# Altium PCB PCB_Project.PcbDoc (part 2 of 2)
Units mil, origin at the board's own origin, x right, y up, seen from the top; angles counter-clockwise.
Board outline 2079.64 x 1653.54 mil, 2 copper layers (Top Layer, Bottom Layer), stack 62 mil thick; 65 components, 34 nets, 154 pads, 107 vias.
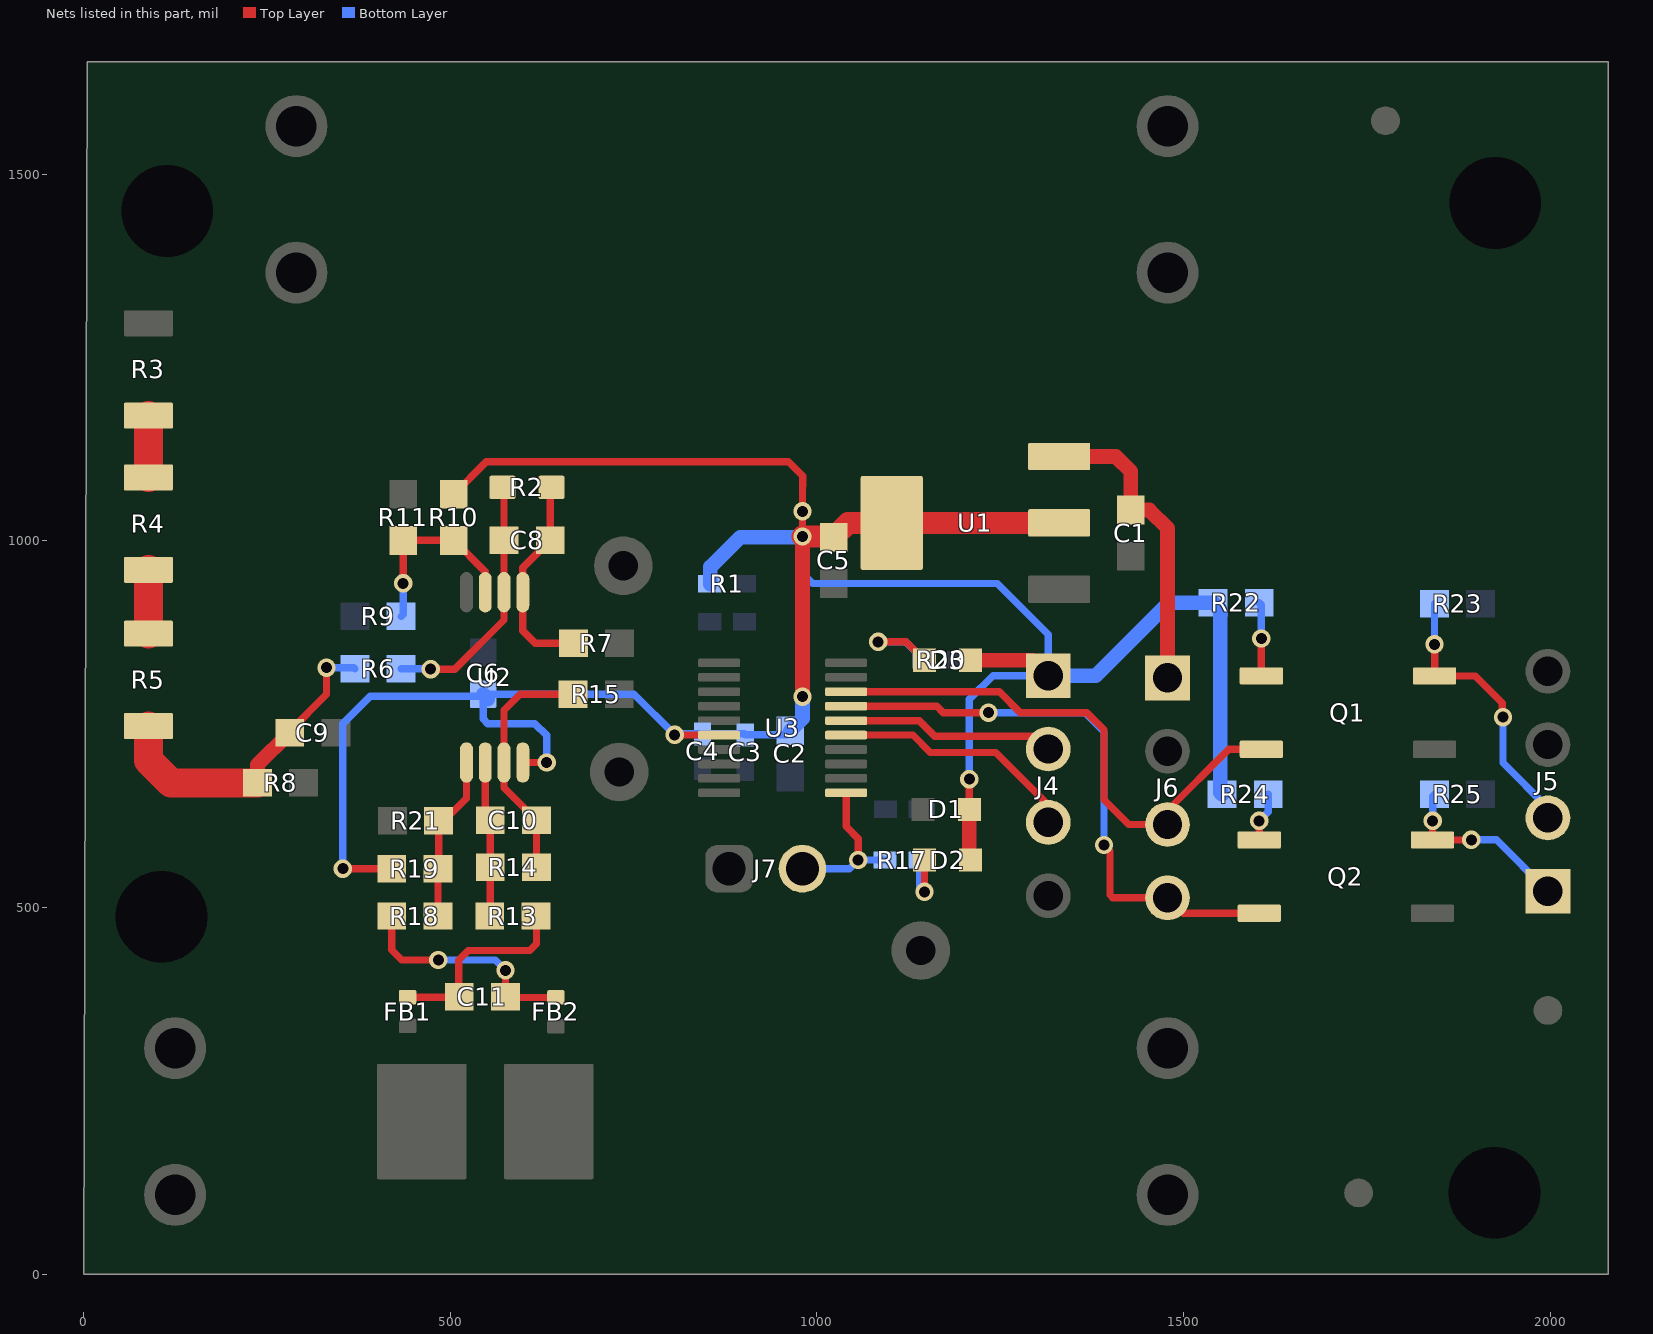
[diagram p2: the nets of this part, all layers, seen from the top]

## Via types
v1: diameter 25, hole 15, Top Layer to Bottom Layer, tented both sides, 107 vias

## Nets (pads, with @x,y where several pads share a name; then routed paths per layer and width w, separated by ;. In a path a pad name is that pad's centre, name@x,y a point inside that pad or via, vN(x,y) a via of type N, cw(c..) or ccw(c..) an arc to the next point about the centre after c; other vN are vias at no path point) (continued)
NetC8_1: C8.1 R2.2 R7.1 U2.1 | length 287.9
  Top Layer w10: R2.2@638.16,1072.92 636.43,1071.19 C8.1@636.43,1000.5 599.03,963.1 U2.1@599.03,929.88 599.03,877.36 616.14,860.25 R7.1@668.08,860.25
NetC8_2: C8.2 R2.1 R6.2 U2.2 | length 350.1
  Top Layer w10: v1(473.48,824.91) 506.4,824.91 573.44,891.95 U2.2@573.44,929.88 C8.2@573.44,1000.5 573.44,1070.71 R2.1@571.23,1072.92
  Bottom Layer w10: R6.2@433.13,825.31 473.08,825.31 v1(473.48,824.91)
NetC9_1: C9.1 R5.2 R6.1 R8.2 | length 433.3
  Top Layer w10: C9.1@281.17,738.28 281.17,740.3 331.36,790.49 v1(331.36,826.82)
  Top Layer w20: R8.2@237.21,669.75 237.21,694.32 C9.1@281.17,738.28
  Top Layer w40: R5.2@88.58,747.3 88.58,700.41 119.25,669.75 R8.2@237.21,669.75
  Bottom Layer w10: v1@341.8,826.82 368.63,826.82 R6.1@370.14,825.31
NetC10_1: C10.1 R14.2 R15.1 U2.7 | length 335.8
  Top Layer w10: R14.2@617.73,554.78 C10.1@617.73,618.76 573.44,663.05 U2.7@573.44,697.59 573.44,769.06 595.13,790.76 R15.1@667.63,790.76
NetC10_2: C10.2 R13.2 R14.1 U2.6 | length 212.5
  Top Layer w10: U2.6@547.85,697.59 547.85,625.65 C10.2@554.74,618.76 R14.1@554.74,554.78 554.74,489.06 R13.2@553.93,488.25
NetC11_1: C11.1 FB1.1 R13.1 | length 273.4
  Top Layer w10: FB1.1@441.99,377.66 511.9,377.66 C11.1@512.41,378.17 ; C11.1@511.83,378.76 511.83,428.3 524.82,441.29 608.61,441.29 617.73,450.41 617.73,487.45 R13.1@616.92,488.25
NetC11_2: C11.2 FB2.1 R18.1 | length 323.1
  Top Layer w10: R18.1@420.33,488.25 420.33,441.81 433.84,428.3 v1(483.93,428.3) v1@486.44,430.81 ; v1(575.41,414.23) 576.39,414.23 575.41,413.25 C11.2@575.41,378.17 576.39,377.19 FB2.1@644.14,377.19
  Bottom Layer w10: v1(483.93,428.3) 561.34,428.3 v1(575.41,414.23)
NetD3_1: D3.1 R20.2 | length 146.1
  Top Layer w10: v1(1083.66,862.2) 1121.61,862.2 D3.1@1146.8,837.02
  Bottom Layer w10: v1(1083.66,862.2) 1121.32,862.2 R20.2@1145.95,837.58
NetQ1_1: Q1.1 R22.2 | length 101.1
  Top Layer w10: Q1.1@1606.3,815.62 v1(1606.3,866.75)
  Bottom Layer w10: R22.2@1603.35,915.46 1606.3,912.5 v1(1606.3,866.75)
NetQ2_1: Q2.1 R24.2 | length 67.4
  Top Layer w10: Q2.1@1603.35,591.97 v1(1603.35,618.01)
  Bottom Layer w10: v1(1603.35,618.01) 1615.68,630.34 R24.2@1615.68,654.26
NetR3_1: R3.1 R4.2 | length 84.2
  Top Layer w40: R4.2@88.58,1086.33 R3.1@88.58,1170.57
NetR4_1: R4.1 R5.1 | length 87.1
  Top Layer w40: R5.1@88.58,873.29 R4.1@88.58,960.35
NetR9_2: R9.2 R10.1 R11.2 U2.3 | length 262.5
  Top Layer w10: v1(435.85,941.87) R11.2@435.85,1000.51 R10.1@505.14,1000.5 547.85,957.8 U2.3@547.85,929.88
  Bottom Layer w10: R9.2@433.13,896.79 435.85,899.51 v1(435.85,941.87)
NetR18_2: R18.2 R19.2 R21.2 U2.5 | length 229.6
  Top Layer w10: R18.2@483.32,488.25 R19.2@483.32,552.72 484.31,553.7 R21.2@484.31,618.08 491.29,618.08 522.26,649.04 U2.5@522.26,697.59
REACT: J7.2 R17.1 U3.11 | length 216.3
  Top Layer w10: U3.11@1040,656.25 1040,610.3 1056.52,593.78 v1(1056.52,564.54)
  Bottom Layer w10: J7.2@980.39,552.72 1044.7,552.72 v1(1056.52,564.54) R17.1@1093.23,564.54
SWCLK: J4.2 U3.16 | length 291.7
  Top Layer w10: U3.16@1040,754.68 1139.59,754.68 1161.03,733.24 1298.38,733.24 J4.2@1315.7,715.93
SWDIO: J4.3 U3.15 | length 338.9
  Top Layer w10: U3.15@1040,734.99 1131.16,734.99 1154.91,711.24 1244.18,711.24 1315.7,639.72 J4.3@1315.7,615.93
UART0_RX: J6.4 Q2.2 U3.17 | length 806.1
  Top Layer w10: U3.17@1040,774.36 1163.88,774.36 1172.62,765.62 v1(1234.25,765.62) ; v1(1391.73,585.04) 1399.8,576.97 1399.8,516.8 1403.61,512.99 J6.4@1478.35,512.99 1499.37,491.97 Q2.2@1603.35,491.97
  Bottom Layer w10: v1(1234.25,765.62) 1365.7,765.62 1391.73,739.58 v1(1391.73,585.04)
UART0_TX: J6.3 Q1.2 U3.18 | length 750.9
  Top Layer w10: U3.18@1040,794.05 1249.07,794.05 1277.5,765.62 1368.24,765.62 1391.73,742.13 1391.73,646.88 1425.61,612.99 J6.3@1478.35,612.99 1478.35,632.22 1561.75,715.62 Q1.2@1606.3,715.62
UART_ISO_RX: J5.2 Q1.4 R23.1 | length 389
  Top Layer w10: v1(1842.35,858.67) 1842.52,858.5 Q1.4@1842.52,815.62 1897.96,815.62 1934.87,778.71 1934.87,759.37 v1(1935.71,759.37)
  Bottom Layer w10: v1(1842.35,858.67) R23.1@1842.35,914 ; v1(1935.71,759.37) 1935.71,697.38 1997.05,636.05 J5.2@1997.05,622.05
UART_ISO_TX: J5.1 Q2.4 R25.1 | length 250.3
  Top Layer w10: v1(1839.84,618.01) 1839.57,617.73 Q2.4@1839.57,591.97 v1@1883.56,591.97 ; v1@1883.78,591.76 v1@1883.56,591.97 ; v1(1892.55,592.1) 1892.41,591.97 v1@1883.56,591.97
  Bottom Layer w10: v1(1839.84,618.01) 1839.84,651.75 R25.1@1842.35,654.26 ; v1(1892.55,592.1) 1926.99,592.1 J5.1@1997.05,522.05
VDD_3V3: C2.1 C3.1 C4.2 C5.1 C6.1 D1.2 D2.2 D3.2 J4.1 R1.2 R10.2 R19.1 R22.1 R24.1 U1.2 U1.4 U2.8 U3.6 | length 4021.6
  Top Layer w10: v1(353.58,552.72) R19.1@420.33,552.72 ; R10.2@505.14,1063.5 549.29,1107.64 961.49,1107.64 980.91,1088.22 980.91,1074.89 980.56,1074.53 v1(980.56,1040.2) v1(980.56,1005.86) ; U2.8@599.03,697.59 v1(631.51,697.59) ; v1@816.97,734.65 817.32,734.99 U3.6@866.77,734.99 ; D1.2@1207.97,633.76 v1(1207.97,674.95)
  Top Layer w20: v1(980.39,787.37) 980.39,1005.69 v1(980.56,1005.86) ; D1.2@1207.97,633.76 1207.97,566.36 D2.2@1209.79,564.54 ; D3.2@1209.79,837.02 1294.61,837.02 J4.1@1315.7,815.93
  Top Layer w30: v1(980.56,1005.86) 1021.95,1005.86 C5.1@1023.08,1004.74 1042.69,1024.35 U1.4@1102.23,1024.35 U1.2@1330.58,1024.35
  Bottom Layer w10: v1(353.58,552.72) 353.58,750.66 390.81,787.88 542.08,787.88 C6.1@544.95,790.76 ; v1(631.51,697.59) 631.51,734.65 615.5,750.66 551.43,750.66 544.95,757.13 C6.1@544.95,790.76 ; C2.1@963.83,740.9 958.18,735.25 C3.1@902.4,735.25 901.03,736.62 C4.2@844.24,736.62 807.59,736.62 v1(806.22,735.25) 750.72,790.76 C6.1@544.95,790.76 ; v1(980.56,1005.86) 980.56,955.56 994.38,941.74 1246.07,941.74 1315.7,872.12 J4.1@1315.7,815.93 1240.25,815.93 1207.97,783.65 v1(1207.97,674.95)
  Bottom Layer w20: C6.1@544.95,790.76 C6.1@551.44,784.27 ; R1.2@854.91,940.81 854.91,964.13 895.52,1004.74 979.44,1004.74 v1(980.56,1005.86) ; C2.1@963.83,740.9 980.56,757.63 980.56,787.2 v1(980.39,787.37) ; J4.1@1315.7,815.93 1380.51,815.93 1480.04,915.46 R22.1@1540.35,915.46 1550.18,905.63 1550.18,656.76 R24.1@1552.69,654.26
VIN: C1.1 J6.1 U1.3 | length 423.3
  Top Layer w20: U1.3@1330.58,1114.9 1408.01,1114.9 1428.35,1094.56 C1.1@1428.35,1041.84 1453.7,1041.84 1478.35,1017.2 J6.1@1478.35,812.99
YLED: D2.1 R17.2 | length 89.2
  Top Layer w10: v1(1146.8,521.26) D2.1@1146.8,564.54
  Bottom Layer w10: R17.2@1140.48,564.54 1140.48,527.58 v1(1146.8,521.26)
pads on no net: FID1.1 FID2.1 FID3.1 MH1.1 MH2.1 MH3.1 MH4.1 U3.3 U3.4 U3.8 U3.9 U3.10 U3.13 U3.14 U3.19 U3.20

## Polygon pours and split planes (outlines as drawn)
A_Netural_OUT on Top Layer "TOP_LAYER_A_NETURAL_OUT_P006" (solid, remove dead copper, pour order 6): 578.36,359.47 1528.35,359.47 1528.35,27.36 1526.08,25.1 577.91,25.1 578.36,25.55
A_Netural_IN on Top Layer "TOP_LAYER_A_NETURAL_IN_P004" (solid, remove dead copper, pour order 4): 52.17,394.91 276.69,394.91 278.66,396.87 278.66,1156.24 1528.35,1156.24 1528.35,388.12 525.21,388.12 525.21,28.06 522.64,25.49 522.54,25.59 50.2,25.59 50.2,392.94
A_LIN_IN on Top Layer "TOP_LAYER_A_LIN_IN_P001" (solid, remove dead copper, pour order 1): 219.49,1637.8 1535.83,1637.8 1535.83,1317.91 219.49,1317.91
VDD_3V3 on Top Layer "TOP_LAYER_VDD_3V3_P000" (solid, remove dead copper, pour order 0): 845.67,1016.84 915.81,1086.98 1143.57,1086.98 1143.57,941.74 845.67,941.74
A_Netural_OUT on Bottom Layer "BOTTOM_LAYER_A_NETURAL_OUT_P007" (solid, remove dead copper, pour order 7): 578.36,359.47 1528.35,359.47 1528.35,27.36 580.81,27.36 578.54,25.1 578.36,25.28
A_LIN_IN on Bottom Layer "BOTTOM_LAYER_A_LIN_IN_P005" (solid, remove dead copper, pour order 5): 219.49,1628.05 1535.83,1628.05 1535.83,1317.91 219.49,1317.91 219.49,1628.05
A_Netural_IN on Bottom Layer "BOTTOM_LAYER_A_NETURAL_IN_P003" (solid, remove dead copper, pour order 3): 51.18,25.59 52.17,24.61 522.64,24.61 522.64,377.79 512.31,388.12 1528.35,388.12 1528.35,1156.24 278.66,1156.24 278.66,396.87 54.13,396.87 50.2,392.94 50.2,25.59

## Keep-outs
Keep-Out Layer:
  text ".Layer_Name" at 577,-858.49 h60

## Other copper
Top Layer:
  text ".Layer_Name" at 577,-858.49 h60
Bottom Layer:
  text ".Layer_Name" at 577,-858.49 h60

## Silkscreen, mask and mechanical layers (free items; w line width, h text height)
Top Overlay:
  text "Live_IN" at 383.58,1449.8 h60
  text "Live_OUT" at 1170,1437.99 h60
  text "3V3" at 1253.55,797.22 h30 r90
  text "VIN" at 1417.9,792.83 h30 r90
  text "ISO_VDD" at 1932.35,761.84 h30 r90
  text "CLK" at 1253.68,688.34 h30 r90
  text "GND" at 1419.87,683.29 h30 r90
  text "GND" at 1937.86,681.98 h30 r90
  text "RX" at 1933.34,598 h30 r90
  text "TX" at 1419.23,595.4 h30 r90
  text "DIO" at 1253.68,592.94 h30 r90
  text "TX" at 1929.07,498.39 h30 r90
  text "GND" at 1253.68,494.07 h30 r90
  text "RX" at 1417.59,491.7 h30 r90
  text "Neutral_OUT" at 1092.42,192.38 h60
  text "Neutral_IN" at 194.88,54.13 h60
  text "E-metering with M0C" at 777.95,47.15 h70
  text ".Layer_Name" at 577,-858.49 h60
Bottom Overlay:
  text ".Layer_Name" at 577,-858.49 h60
Top Paste:
  text ".Layer_Name" at 577,-858.49 h60
Bottom Paste:
  text ".Layer_Name" at 577,-858.49 h60
Top Solder:
  text ".Layer_Name" at 577,-858.49 h60
  text ".Layer_Name" at 577,-858.49 h60
Bottom Solder:
  text ".Layer_Name" at 577,-858.49 h60
Drill Guide:
  text ".Layer_Name" at 577,-858.49 h60
M1 Board Outline:
  the board outline again, w10
  text ".Layer_Name" at 577,-858.49 h60
M2 Board Dimensions:
  rectangle: 125,-400 500,-275
  rectangle: 0,-275 125,-150
  lines w7: 0,-275 1000,-275 ; 125,-400 125,-150 ; 250,-400 250,-150 ; 500,-400 500,-150 ; 750,-400 750,-150 ; 0,-400 0,-150 1000,-150 1000,-400 0,-400
  text ".Layer_Name" at 577,-858.49 h60
M3 3D STEP Top:
  text ".Layer_Name" at 577,-858.49 h60
M4 3D STEP Bottom:
  text ".Layer_Name" at 577,-858.49 h60
M5 Assembly Top:
  lines w10: -292,-930.17 6308,-930.17 ; -292,-726.83 6310,-726.83 ; -292,-523.5 -292,-1133.5 3713,-1133.5 6310,-1133.5 6310,-523.5 -291.5,-523.5 -291.5,-1133.5 1284,-1133.5 ; 2173,-1133.5 2173,-523.5 ; 3440,-726.83 3440,-523.5 ; 4280,-726.83 4280,-523.5 ; 4902,-1140 4902,-937.17
  text "COMPONENTS MARKED 'DNP' SHOULD NOT BE POPULATED." at 1153.5,-318.5 h60
  text "ASSEMBLY VARIANT:" at 1153,-434 h60
  text ".VariantName" at 2189,-434 h60
  text "PCB VIEWED FROM TOP SIDE" at -228.5,-655.67 h60
  text "BOARD #:" at 2248,-655.67 h60
  text ".PRJ_Number" at 2793.5,-655.67 h60
  text "REV:" at 3638,-655.67 h60
  text ".PCB_Rev" at 3929.5,-655.67 h60
  text "SVN REV:" at 4476,-655.67 h60
  text ".VersionControl_RevNumber" at 4982,-655.67 h60
  text "PLOT NAME =" at -228.5,-1064.34 h60
  text ".plot_File_Name" at 577,-1064.34 h60
  text "GENERATED    :" at 2250,-1064.34 h60
  text ".Print_Date" at 3119.5,-1064.34 h60
  text ".Print_Time" at 3848.5,-1064.34 h60
  text "TEXAS INSTRUMENTS" at 5113,-1064.34 h60
M6 Assembly Bottom:
  lines w10: -292.5,-727.33 6309.5,-727.33 ; -290.5,-930.67 6309.5,-930.67 ; 1115.5,-1140.5 1115.5,-937.67 ; 1737.5,-727.33 1737.5,-524 ; 2577.5,-727.33 2577.5,-524 ; 3844.5,-1134 3844.5,-524 ; 4733.5,-1134 6309,-1134 6309,-524 -292.5,-524 -292.5,-1134 2304.5,-1134 6309.5,-1134 6309.5,-524
  text "COMPONENTS MARKED 'DNP' SHOULD NOT BE POPULATED." at 6102,-318 h60
  text ".VariantName" at 5058,-434 h60
  text "ASSEMBLY VARIANT:" at 6097,-434 h60
  text ".VersionControl_RevNumber" at 1035.5,-656.17 h60
  text "SVN REV:" at 1541.5,-656.17 h60
  text ".PCB_Rev" at 2088,-656.17 h60
  text "REV:" at 2379.5,-656.17 h60
  text ".PRJ_Number" at 3224,-656.17 h60
  text "BOARD #:" at 3769.5,-656.17 h60
  text "PCB VIEWED FROM BOTTOM SIDE" at 6246,-656.17 h60
  text "TEXAS INSTRUMENTS" at 904.5,-1064.84 h60
  text ".Print_Time" at 2169,-1064.84 h60
  text ".Print_Date" at 2898,-1064.84 h60
  text "GENERATED    :" at 3767.5,-1064.84 h60
  text ".plot_File_Name" at 5440.5,-1064.84 h60
  text "PLOT NAME =" at 6246,-1064.84 h60
M9 Title Sheet:
  drawing of 56 lines, arcs and shapes, not listed
  text "1" at 1058.34,13381.39 h70
  text "2" at 4384,13381.39 h70
  text "3" at 7714,13381.39 h70
  text "4" at 11049,13381.39 h70
  text "5" at 14374,13381.39 h70
  text "6" at 17709,13381.39 h70
  text "A" at -463,11603.39 h70
  text "A" at 19237,11603.39 h70
  text "B" at -463,7853.39 h70
  text "B" at 19237,7853.39 h70
  text "C" at -463,4103.39 h70
  text "C" at 19237,4103.39 h70
  text "D" at -463,353.39 h70
  text "D" at 19237,353.39 h70
  text "PROJECT TITLE:" at 16143,268.39 h45
  text ".PRJ_Title" at 16193,135.06 h70
  text "DESIGNED FOR:" at 16143,-32.61 h45
  text ".PRJ_Customer" at 16193,-172.61 h70
  text "FILE NAME:" at 16143,-332.61 h45
  text ".PCB_File_Name_No_Path" at 16193,-452.61 h70
  text "Texas Instruments (TI) and/or its licensors do not warrant the accuracy or completeness of this specification" at 11173.5,-614.45 h45
  text "ENGINEER:" at 16143,-622.61 h45
  text "LAYOUT BY:" at 17648,-622.61 h45
  text "or any information contained therein. TI and/or its licensors do not warrant that this design will meet" at 11128.51,-727.11 h45
  text ".PRJ_Engineer" at 16193,-777.6 h70
  text ".PCB_Layout" at 17698.5,-777.6 h70
  text "the specifications, will be suitable for your application or fit for any particular purpose, or will operate in" at 11128.51,-839.78 h45
  text ".Layer_Name" at 577,-858.49 h60
  text "ALTIUM DESIGNER VERSION:" at 17648,-932.61 h45
  text "an implementation. TI and/or its licensors do not warrant that the design is production worthy. You should" at 11128.51,-952.44 h45
  text "completely validate and test your design implementation to confirm the system functionality for your application." at 11173.5,-1065.11 h45
  text ".print_Scale" at 16193,-1065.94 h70
  text ".Application_BuildNumber" at 17698.5,-1065.94 h70
  text "1" at 1058.34,-1318.61 h70
  text "2" at 4384,-1318.61 h70
  text "3" at 7714,-1318.61 h70
  text "4" at 11049,-1318.61 h70
  text "5" at 14374,-1318.61 h70
  text "6" at 17709,-1318.61 h70
M10 Fab Notes:
  drawing of 189 lines, arcs and shapes, not listed
  text "DESIGN INFORMATION" at 17178.02,6365.17 h60
  text "MIN. TRACK WIDTH:" at 16533.46,6233.05 h60
  text "8" at 17629.7,6233.05 h60
  text "MIL" at 17784.46,6233.05 h60
  text "MIN. CLEARANCE:" at 16533.46,6108.92 h60
  text "MIL" at 17784.46,6108.92 h60
  text "7.874" at 17459.65,6104.33 h60
  text "MIN. VIA PAD SIZE:" at 16533.46,5984.8 h60
  text "24" at 17599.71,5984.8 h60
  text "MIL" at 17784.46,5984.8 h60
  text "0.05mm (2MIL)" at 17228.46,5854.9 h60
  text "MINIMUM ANNULAR RING" at 16204.23,5846.67 h60
  text "EXTERNAL" at 17936.46,5846.67 h60
  text "PER" at 16404.23,5736.55 h60
  text "IPC-D-275 CLASS 2 LEVEL C" at 16624.23,5736.54 h60
  text "MIL, HOLES" at 18112.46,5636.07 h60
  text "+/-" at 17720,5627.48 h60
  text "+/-" at 18574,5627.48 h60
  text "REGISTRATION TOLERANCES:" at 16204.23,5626.42 h60
  text "METAL" at 17404,5626.42 h60
  text "5" at 17980.2,5626.42 h60
  text "3" at 18813.2,5626.42 h60
  text "MIL" at 18929.46,5626.42 h60
  text "HOLE SIZE TOLERANCE (UNLESS OTHERWISE SPECIFIED):" at 16204.23,5528.1 h60
  text "+/-" at 18574,5525.23 h60
  text "3" at 18813.2,5524.17 h60
  text "MIL" at 18929.46,5524.17 h60
  text "MATERIAL:" at 16129.46,5386.52 h60
  text "FR-4 High Tg" at 17115.9,5258 h60
  text "X" at 16971.46,5250.01 h60
  text "FR-4" at 16550.46,5245.49 h60
  text "OTHER" at 18038.46,5245.49 h60
  text "62 MIL (1.6mm) +/-10%" at 16870.56,5102.46 h60
  text "X" at 16750.46,5100.01 h60
  text "THICKNESS:" at 16204.23,5094.24 h60
  text "OTHER" at 18155.46,5094.24 h60
  text "TOLERANCE:" at 16204.23,4955.92 h60
  text "X" at 17052.46,4955.92 h60
  text "ANSI IPC-6012 TYPE 3 CLASS 2" at 17230.48,4955.92 h60
  text "OTHER +/-" at 17230.46,4811.73 h60
  text "BOW & TWIST:" at 16204.23,4666.54 h60
  text "X" at 17052.46,4666.54 h60
  text "ANSI IPC-6012 TYPE 3 CLASS 2" at 17230.48,4666.54 h60
  text "OTHER +/-" at 17230.46,4519.85 h60
  text "DRILLING:" at 16129.46,4389.23 h60
  text "NC_DRILL FILES" at 17890.46,4284.04 h60
  text "REFERENCE:" at 16204.23,4280.1 h60
  text "X" at 16861.46,4280.01 h60
  text "AS SHOWN" at 17039.46,4280.1 h60
  text "X" at 17762.46,4280.1 h60
  text "OTHER" at 18188.46,4137.85 h60
  text "PTH COPPER THICKNESS:" at 16203.91,4134.32 h60
  text "X" at 17343.14,4134.32 h60
  text "20-30 um" at 17471.14,4134.32 h60
  text "BOARD FINISH:" at 16129.46,3986.73 h60
  text "SILKSCREEN:" at 16284.68,3876.6 h60
  text "X" at 17242.46,3876.6 h60
  text "TOP" at 17359.46,3876.6 h60
  text "X" at 17752.46,3876.6 h60
  text "BOTTOM" at 17870.46,3876.6 h60
  text "SILKSCREEN COLOR:" at 16284.68,3721.41 h60
  text "X" at 17241.46,3721.41 h60
  text "WHITE" at 17359.46,3721.41 h60
  text "OTHER" at 17870.46,3721.41 h60
  text "X" at 17372.46,3577.96 h60
  text "GREEN" at 17490.46,3577.96 h60
  text "OTHER" at 18108.46,3577.96 h60
  text "SOLDER RESIST COLOR:" at 16284.68,3571.1 h60
  text "X" at 17372.46,3423.71 h60
  text "MATTE" at 17490.46,3423.71 h60
  text "SEMI-GLOSS" at 18108,3423.07 h60
  text "IMMERSION GOLD (ENIG)" at 17190.46,3250.94 h60
  text "ENEPIG" at 18528,3243.72 h60
  text "SURFACE FINISH:" at 16129.46,3242.72 h60
  text "X" at 17012.46,3242.72 h60
  text "IMM. TIN/SILVER OR EQUIV" at 16459,3105.4 h60
  text "OTHER" at 17890.46,3101.47 h60
  text "ARRAY/PANEL:" at 16129.46,2946.09 h60
  text "CUT AND TRIM PER M1 BOARD OUTLINE" at 17190.46,2937.87 h60
  text "N.C. ROUTE" at 17190.46,2801.9 h60
  text "X" at 17878.46,2801.9 h60
  text "V. SCORE" at 18056.46,2801.9 h60
  text "CERTIFICATION:" at 16129.46,2672.77 h60
  text "MATERIALS AND WORKMANSHIP FOR ALL PCBS" at 16854.46,2672.77 h60
  text "TO MEET OR EXCEED THE REQUIREMENTS OF:" at 16854.46,2578.71 h60
  text "X" at 16491.97,2450.08 h60
  text "ANSI IPC-A-600F CLASS ->" at 16619.96,2450.08 h60
  text "X" at 18267.97,2450.08 h60
  text "2" at 18377.96,2450.08 h60
  text "1" at 18062.96,2448.58 h60
  text "3" at 18731.96,2448.58 h60
  text "X" at 17303.97,2302.39 h60
  text "RoHS" at 17431.96,2302.39 h60
  text "OTHER" at 18076.36,2302.39 h60
  text "PER ORDER" at 18473.42,2302.39 h60
  text "ALL BOARDS MUST MEET OR EXCEED UL94-V0 REQUIREMENTS." at 16157,2148.57 h60
  text "PCB MUST BEAR THE UL94V-0 UL REGISTERED MATERIAL ID NUMBER" at 16157,2032.5 h60
  text "ADDITIONAL REQUIREMENTS:" at 16129.46,1863.08 h60
  text "MICROSECTION:" at 16204.23,1755.95 h60
  text "YES" at 17109.96,1755.95 h60
  text "REQUIRED" at 17971.46,1611.62 h60
  text "BARE BOARD ELEC. TEST:" at 16204.23,1608.76 h60
  text "NONE" at 17509.96,1608.76 h60
  text "X" at 17853.46,1608.76 h60
  text "PER ORDER" at 18563.46,1608.76 h60
  text "XX MIL VIAS REQUIRE NON-CONDUCTIVE FILL AND PLANARIZE" at 16372.38,1403.82 h59
  text "XX MIL VIAS REQUIRE CONDUCTIVE FILL AND PLANARIZE" at 16380.38,1299.84 h60
  text "OUTER XX MIL TRACES REQUIRE 50 OHM SINGLE-ENDED IMPEDANCE" at 16379.39,1136.46 h58
  text "LAYER 2 & 3 (INNER LAYERS) XX MIL WIDE, XX MIL SPACE / TRACES REQUIRE 100 OHM DIFFERENTIAL IMPEDANCE" at 16371.39,900.74 h60
  text ".Layer_Name" at 577,-858.49 h60
M11 Gerber Information:
  lines w10: -292,-930.17 6308,-930.17 ; -292,-726.83 6310,-726.83 ; -292,-523.5 -292,-1133.5 3713,-1133.5 6310,-1133.5 6310,-523.5 -291.5,-523.5 -291.5,-1133.5 1284,-1133.5 ; 2173,-1133.5 2173,-523.5 ; 3440,-726.83 3440,-523.5 ; 4280,-726.83 4280,-523.5 ; 4902,-1140 4902,-937.17
  text "ALL ARTWORK VIEWED FROM TOP SIDE" at -228.5,-655.67 h60
  text "BOARD #:" at 2248,-655.67 h60
  text ".PRJ_Number" at 2793.5,-655.67 h60
  text "REV:" at 3638,-655.67 h60
  text ".PCB_Rev" at 3929.5,-655.67 h60
  text "SVN REV:" at 4476,-655.67 h60
  text ".VersionControl_RevNumber" at 4982,-655.67 h60
  text "LAYER NAME =" at -228.5,-858.49 h60
  text "PLOT NAME =" at -228.5,-1064.34 h60
  text ".plot_File_Name" at 577,-1064.34 h60
  text "GENERATED    :" at 2250,-1064.34 h60
  text ".Print_Date" at 3119.5,-1064.34 h60
  text ".Print_Time" at 3848.5,-1064.34 h60
  text "TEXAS INSTRUMENTS" at 5113,-1064.34 h60
M12 Stackup:
  drawing of 191 lines, arcs and shapes, not listed
  text "Layer" at 14605.06,13091.48 h60
  text "Name" at 15014.97,13091.48 h60
  text "Material" at 15944.72,13091.48 h60
  text "Thickness" at 16804.48,13091.48 h60
  text "Constant" at 17454.32,13091.48 h60
  text "Board Layer Stack" at 18024.18,13091.48 h60
  text "Top Overlay" at 15014.97,12971.48 h60
  text "Top Solder" at 15014.97,12851.48 h60
  text "Solder Resist" at 15944.72,12851.48 h60
  text "0.40mil" at 16804.48,12851.48 h60
  text "3.5" at 17454.32,12851.48 h60
  text "1" at 14605.06,12731.48 h60
  text "Top Layer" at 15014.97,12731.48 h60
  text "1.40mil" at 16804.48,12731.48 h60
  text "Dielectric1" at 15014.97,12611.48 h60
  text "FR-4 High Tg" at 15944.72,12611.48 h60
  text "59.20mil" at 16804.48,12611.48 h60
  text "4.8" at 17454.32,12611.48 h60
  text "2" at 14605.06,12491.48 h60
  text "Bottom Layer" at 15014.97,12491.48 h60
  text "1.40mil" at 16804.48,12491.48 h60
  text "Bottom Solder" at 15014.97,12371.48 h60
  text "Solder Resist" at 15944.72,12371.48 h60
  text "0.40mil" at 16804.48,12371.48 h60
  text "3.5" at 17454.32,12371.48 h60
  text "Bottom Overlay" at 15014.97,12251.48 h60
  text ".Layer_Name" at 577,-858.49 h60
M13 Component Bodies Top:
  text ".Layer_Name" at 577,-858.49 h60
M14 Component Bodies Bottom:
  text ".Layer_Name" at 577,-858.49 h60
M15 Courtyards Top:
  text ".Layer_Name" at 577,-858.49 h60
M16 Courtyards Bottom:
  text ".Layer_Name" at 577,-858.49 h60
Drill Drawing:
  circle w10: c5443.72,3159.96 r27.63
  lines w10: 5416.09,2814.63 5471.34,2814.63 5443.72,2759.38 5416.09,2814.63 ; 5416.09,2883.7 5471.34,2883.7 5471.34,2938.95 5416.09,2938.95 5416.09,2883.7 ; 5416.09,3021.83 5429.9,3021.83 5443.72,3008.02 5457.53,3021.83 5471.34,3021.83 5457.53,3035.64 5471.34,3049.46 5457.53,3049.46 5443.72,3063.27 5429.9,3049.46 5416.09,3049.46 5429.9,3035.64 5416.09,3021.83 ; 5416.09,3256.66 5443.72,3270.47 5471.34,3256.66 5457.53,3284.28 5471.34,3311.91 5443.72,3298.1 5416.09,3311.91 5429.9,3284.28 5416.09,3256.66
  lines w12: 5366,2722.08 8597.49,2722.08 ; 5366,3343.68 8597.49,3343.68 ; 5703.86,2597.76 5703.86,3468 ; 6035.86,2597.76 6035.86,3468 ; 6672.43,2597.76 6672.43,3468 ; 6931.57,2597.76 6931.57,3468 ; 7306.72,2597.76 7306.72,3468 ; 8031.05,2597.76 8031.05,3468 ; 5366,2597.76 8597.49,2597.76 8597.49,3468 5366,3468 5366,2597.76
  text "Symbol" at 5440.59,3380.98 h72
  text "Quantity" at 5741.16,3380.98 h72
  text "Finished Hole Size" at 6073.16,3380.98 h72
  text "Plated" at 6709.72,3380.98 h72
  text "Hole Type" at 6968.86,3380.98 h72
  text "Drill Layer Pair" at 7344.02,3380.98 h72
  text "Hole Tolerance" at 8068.35,3380.98 h72
  text "4" at 5741.16,3256.66 h60
  text "125.00mil (3.175mm)" at 6073.16,3256.66 h60
  text "NPTH" at 6709.72,3256.66 h60
  text "Round" at 6968.86,3256.66 h60
  text "Top Layer - Bottom Layer" at 7344.02,3256.66 h60
  text "107" at 5741.16,3132.34 h60
  text "15.00mil (0.381mm)" at 6073.16,3132.34 h60
  text "PTH" at 6709.72,3132.34 h60
  text "Round" at 6968.86,3132.34 h60
  text "Top Layer - Bottom Layer" at 7344.02,3132.34 h60
  text "15" at 5741.16,3008.02 h60
  text "40.00mil (1.016mm)" at 6073.16,3008.02 h60
  text "PTH" at 6709.72,3008.02 h60
  text "Round" at 6968.86,3008.02 h60
  text "Top Layer - Bottom Layer" at 7344.02,3008.02 h60
  text "2" at 5741.16,2883.7 h60
  text "45.28mil (1.150mm)" at 6073.16,2883.7 h60
  text "PTH" at 6709.72,2883.7 h60
  text "Round" at 6968.86,2883.7 h60
  text "Top Layer - Bottom Layer" at 7344.02,2883.7 h60
  text "8" at 5741.16,2759.38 h60
  text "55.12mil (1.400mm)" at 6073.16,2759.38 h60
  text "PTH" at 6709.72,2759.38 h60
  text "Round" at 6968.86,2759.38 h60
  text "Top Layer - Bottom Layer" at 7344.02,2759.38 h60
  text "136 Total" at 5741.16,2635.06 h60
  text ".Layer_Name" at 577,-858.49 h60
M17 Embedded Cavity:
  text ".Layer_Name" at 577,-858.49 h60
M18 Embedded Assembly:
  text ".Layer_Name" at 577,-858.49 h60
M19 Embedded Keepout:
  text ".Layer_Name" at 567,-858.49 h60

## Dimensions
0,-400 to 1000,-400 on M2 Board Dimensions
